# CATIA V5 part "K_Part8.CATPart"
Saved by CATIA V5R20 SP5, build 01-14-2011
Part number: squelette_général
Publications: "Plan.1", "Point_origine", "Point_centre_liaison_pivot12", "Point_centre_liaison_pivot23", "Point.4", "point_centre_liaison_glissière", "Point_centre_liaison_pivot_rouleau", "Point.7", "Plan.2", "Plan.3", "Plan.4", "Plan.5", "Droite.1"
Bounding box of the stored display mesh (mm): x 0 to 100, y -40 to 0, z 0 to 150
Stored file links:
  G:\Khaled_CFAO_2011\SIL\SIL_GR2\pfradet\pfradet\Khaled\CAD_ThinkMOTION\K_Part8.CATPart
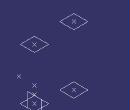
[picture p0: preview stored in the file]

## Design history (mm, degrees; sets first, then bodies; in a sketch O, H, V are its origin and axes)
Set1
  Plane1 "Plan_référence": type Offset, RefPlane xy-plane, Offset 0
  Point1 "Point_origine": (0, 0, 0)
  Point2 "Point_centre_liaison_pivot12": (0, 0, 150)
  Point3 "Point_centre_liaison_pivot23": (100, 0, 150)
  Point4: (100, 0, 20)
  Point5 "point_centre_liaison_glissière": (100, 0, 40)
  Point6 "Point_centre_liaison_bras3_rouleau": (100, -40, 60)
  Point7: (100, 0, 60)
  Plane2: type OffsetPt, RefPlane Plane1, RefPoint Point3
  Plane3: type OffsetPt, RefPlane Plane1, RefPoint Point4
  Plane4: type OffsetPt, RefPlane yz-plane, RefPoint Point4
  Plane5: type OffsetPt, RefPlane Plane1, RefPoint Point2
Body1 (main body)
